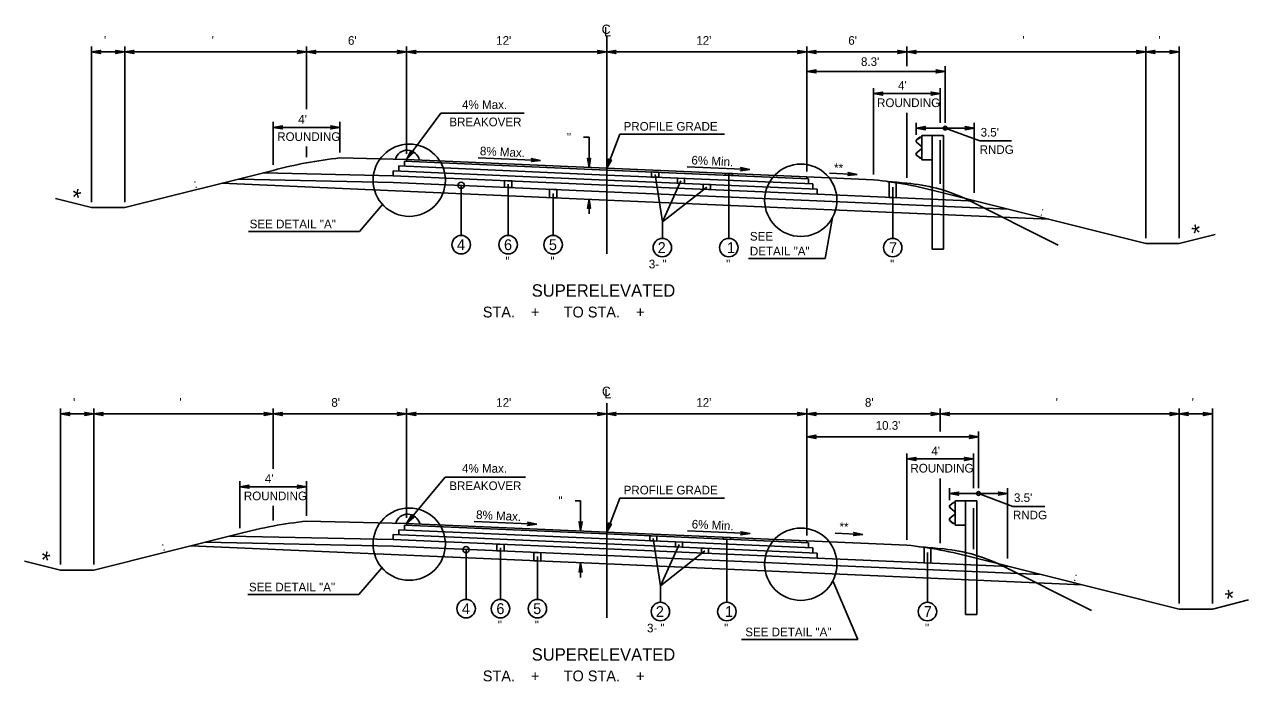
# Model space of a CAD drawing. Extents: x -540 to 1231, y -564 to 421.
# Drawn here: x 1028.3 to 1226.1, y -243.2 to -137 of the extents above; entities that cross this region are included whole.
import ezdxf

# ---------------------------------------------------------------- set-up
doc = ezdxf.new("R2010")
doc.units = 0
doc.layers.add('1', color=7, linetype='Continuous')
doc.layers.add('Des_ Drain_ Ftrs', color=7, linetype='Continuous')

msp = doc.modelspace()

# ---------------------------------------------------------------- linework, layer by layer
at = {"layer": '1'}
for p, q in [((1122.38, -174.05), (1122.38, -138.76)), ((1039.12, -165.67), (1039.12, -140.52)), ((1044.51, -141.4), (1039.12, -141.4)), ((1044.51, -165.67), (1044.51, -140.52)), ((1073.88, -141.4), (1044.51, -141.4)), ((1073.88, -150.65), (1073.88, -140.52)), ((1090.05, -141.4), (1073.88, -141.4)), ((1090.05, -157.9), (1090.05, -140.52)), ((1122.38, -141.4), (1090.05, -141.4)), ((1122.38, -141.4), (1154.71, -141.4)), ((1154.71, -160.72), (1154.71, -140.52)), ((1154.71, -141.4), (1170.87, -141.4)), ((1170.87, -143.69), (1170.87, -140.52)), ((1170.87, -141.4), (1209.46, -141.4)), ((1209.46, -171.5), (1209.46, -140.52)), ((1209.46, -141.4), (1214.85, -141.4)), ((1214.85, -171.5), (1214.85, -140.52)), ((1177.07, -152.84), (1177.07, -143.69)), ((1154.71, -144.57), (1177.07, -144.57)), ((1177.07, -144.57), (1177.07, -151.71)), ((1165.48, -161.2), (1165.48, -147.26)), ((1165.48, -148.14), (1176.26, -148.14)), ((1176.26, -152.84), (1176.26, -147.26)), ((1090.04, -158.78), (1095.58, -151.32)), ((1109.06, -151.32), (1095.58, -151.32)), ((1170.87, -161.75), (1170.87, -151.26)), ((1068.49, -159.68), (1068.49, -152.73)), ((1079.27, -153.61), (1068.49, -153.61)), ((1079.27, -157.66), (1079.27, -152.73)), ((1172.38, -154.79), (1172.38, -152.84)), ((1172.38, -153.72), (1181.76, -153.72)), ((1177.07, -153.72), (1182.63, -155.79)), ((1181.76, -164.19), (1181.76, -152.84)), ((1119.52, -155.19), (1118.64, -155.19)), ((1119.52, -155.19), (1119.52, -160.07)), ((1122.38, -160.19), (1124.48, -154.72)), ((1141.4, -154.72), (1124.48, -154.72)), ((1172.44, -156.01), (1173.17, -156.65)), ((1172.97, -155.19), (1172.46, -155.58)), ((1172.46, -155.99), (1173.19, -156.62)), ((1172.99, -155.22), (1172.48, -155.6)), ((1173.29, -155.13), (1172.97, -155.19)), ((1173.29, -155.16), (1172.99, -155.22)), ((1173.29, -154.91), (1173.29, -158.84)), ((1173.29, -154.91), (1174.97, -154.91)), ((1174.97, -154.91), (1174.97, -173.3)), ((1176.8, -154.91), (1174.97, -154.91)), ((1176.26, -162.72), (1176.26, -155.64)), ((1176.8, -154.91), (1176.8, -173.3)), ((1182.63, -155.79), (1187.78, -155.79)), ((1073.88, -158.44), (1073.88, -156.67)), ((1173.17, -157.1), (1172.44, -157.73)), ((1173.19, -157.12), (1172.46, -157.75)), ((1172.46, -158.16), (1172.97, -158.55)), ((1172.48, -158.14), (1172.99, -158.53)), ((1173.26, -156.83), (1173.26, -156.91)), ((1173.29, -156.83), (1173.29, -156.91)), ((1079.27, -158.54), (1090.04, -158.78)), ((1122.38, -161.3), (1088.78, -159.83)), ((1088.78, -160.64), (1088.78, -159.83)), ((1122.38, -160.49), (1089.7, -159.07)), ((1089.7, -159.87), (1089.7, -159.07)), ((1122.38, -160.19), (1090.04, -158.78)), ((1090.04, -158.78), (1090.04, -159.08)), ((1101.58, -158.51), (1111.69, -158.95)), ((1135.36, -159.98), (1145.47, -160.42)), ((1172.97, -158.55), (1173.29, -158.61)), ((1172.99, -158.53), (1173.29, -158.58)), ((1173.29, -158.84), (1174.97, -158.84)), ((1068.49, -160.56), (1044.51, -166.55)), ((1062.93, -161.95), (1087.86, -162.49)), ((1066.9, -160.95), (1087.87, -161.41)), ((1122.38, -162.11), (1087.86, -160.6)), ((1087.86, -161.41), (1087.86, -160.6)), ((1122.38, -162.92), (1087.87, -161.41)), ((1154.71, -161.61), (1122.38, -160.19)), ((1154.95, -161.91), (1122.38, -160.49)), ((1155.65, -162.75), (1122.38, -161.3)), ((1156.35, -163.59), (1122.38, -162.11)), ((1130.2, -161.24), (1131.36, -168.87)), ((1142.1, -161.21), (1142.1, -171.55)), ((1165.48, -162.08), (1154.71, -161.61)), ((1154.71, -161.61), (1154.71, -161.91)), ((1154.95, -161.91), (1154.95, -162.72)), ((1162.85, -161.21), (1158.35, -161.02)), ((1122.38, -165.35), (1060.19, -162.63)), ((1122.38, -164), (1087.86, -162.49)), ((1098.86, -162.97), (1098.86, -171.08)), ((1106.45, -162.76), (1106.45, -171.08)), ((1156.36, -164.4), (1122.38, -162.92)), ((1156.31, -165.48), (1122.38, -164)), ((1134.37, -162.22), (1131.36, -168.87)), ((1138.55, -163.24), (1131.36, -168.87)), ((1155.65, -162.75), (1155.65, -163.56)), ((1156.35, -163.59), (1156.35, -164.4)), ((1168.58, -163.26), (1168.58, -171.55)), ((1172.38, -162.85), (1172.38, -162.85)), ((1176.26, -164.08), (1209.46, -172.38)), ((1033.3, -165.09), (1039.12, -166.55)), ((1082.43, -170.41), (1086.17, -166.09)), ((1113.72, -164.29), (1113.72, -171.08)), ((1119.52, -165.22), (1119.52, -167.59)), ((1193.78, -168.46), (1122.38, -165.35)), ((1187.24, -166.83), (1156.31, -165.48)), ((1182.01, -165.52), (1156.35, -164.4)), ((1180.26, -165.09), (1195.31, -172.61)), ((1044.51, -166.55), (1039.12, -166.55)), ((1131.36, -168.87), (1131.36, -171.55)), ((1158.86, -168.17), (1157.68, -174.81)), ((1064.5, -170.41), (1082.43, -170.41)), ((1220.67, -170.93), (1214.85, -172.38)), ((1176.8, -173.3), (1174.97, -173.3)), ((1209.46, -172.38), (1214.85, -172.38)), ((1145.27, -174.81), (1157.68, -174.81)), ((1034.14, -224.27), (1034.14, -199.03)), ((1039.52, -224.27), (1039.52, -199.03)), ((1068.49, -208.8), (1068.49, -199.03)), ((1090.05, -216.72), (1090.05, -199.03)), ((1122.38, -232.87), (1122.38, -198.15)), ((1154.71, -219.54), (1154.71, -199.03)), ((1176.26, -202.74), (1176.26, -199.03)), ((1214.85, -230.56), (1214.85, -199.03)), ((1220.23, -230.56), (1220.23, -199.03)), ((1039.52, -199.91), (1034.14, -199.91)), ((1068.49, -199.91), (1039.52, -199.91)), ((1090.05, -199.91), (1068.49, -199.91)), ((1122.38, -199.91), (1090.05, -199.91)), ((1122.38, -199.91), (1154.71, -199.91)), ((1154.71, -199.91), (1176.26, -199.91)), ((1176.26, -199.91), (1214.85, -199.91)), ((1214.85, -199.91), (1220.23, -199.91)), ((1154.71, -203.62), (1182.46, -203.62)), ((1182.46, -211.89), (1182.46, -202.74)), ((1170.87, -220.25), (1170.87, -206.31)), ((1170.87, -207.19), (1181.65, -207.19)), ((1181.65, -211.89), (1181.65, -206.31)), ((1063.11, -218.37), (1063.11, -210.8)), ((1073.88, -216.36), (1073.88, -210.8)), ((1090.04, -217.6), (1096.3, -210.12)), ((1109.27, -210.12), (1096.3, -210.12)), ((1176.26, -220.8), (1176.26, -210.34)), ((1073.88, -211.68), (1063.11, -211.68)), ((1122.38, -219.01), (1124.5, -213.5)), ((1141.42, -213.5), (1124.5, -213.5)), ((1177.76, -213.84), (1177.76, -211.89)), ((1177.76, -212.77), (1187.15, -212.77)), ((1182.46, -212.77), (1188.01, -214.85)), ((1187.15, -223.26), (1187.15, -211.89)), ((1068.49, -217.14), (1068.49, -214.76)), ((1118.15, -213.95), (1117.27, -213.95)), ((1118.15, -213.95), (1118.15, -218.82)), ((1177.83, -215.06), (1178.56, -215.7)), ((1178.36, -214.24), (1177.85, -214.63)), ((1177.85, -215.04), (1178.58, -215.68)), ((1178.37, -214.27), (1177.86, -214.65)), ((1178.68, -214.19), (1178.36, -214.24)), ((1178.68, -214.22), (1178.37, -214.27)), ((1178.68, -213.96), (1178.68, -217.89)), ((1178.68, -213.96), (1180.36, -213.96)), ((1180.36, -213.96), (1180.36, -232.35)), ((1182.19, -213.96), (1180.36, -213.96)), ((1181.65, -221.77), (1181.65, -215.12)), ((1182.19, -213.96), (1182.19, -232.35)), ((1188.01, -214.85), (1193.17, -214.85)), ((1073.88, -217.24), (1090.04, -217.6)), ((1100.95, -217.3), (1111.07, -217.74)), ((1178.56, -216.15), (1177.83, -216.78)), ((1178.58, -216.17), (1177.85, -216.81)), ((1177.85, -217.22), (1178.36, -217.61)), ((1177.86, -217.19), (1178.37, -217.58)), ((1178.65, -215.89), (1178.65, -215.96)), ((1178.68, -215.89), (1178.68, -215.96)), ((1063.11, -219.25), (1039.52, -225.15)), ((1122.38, -220.93), (1087.86, -219.42)), ((1087.86, -220.23), (1087.86, -219.42)), ((1122.38, -220.12), (1088.78, -218.65)), ((1088.78, -219.46), (1088.78, -218.65)), ((1122.38, -219.31), (1089.7, -217.88)), ((1089.7, -218.69), (1089.7, -217.88)), ((1122.38, -219.01), (1090.04, -217.6)), ((1090.04, -217.6), (1090.04, -217.9)), ((1154.71, -220.42), (1122.38, -219.01)), ((1154.95, -220.73), (1122.38, -219.31)), ((1135.42, -218.81), (1145.53, -219.25)), ((1163.75, -219.38), (1159.26, -219.18)), ((1178.36, -217.61), (1178.68, -217.66)), ((1178.37, -217.58), (1178.68, -217.63)), ((1178.68, -217.89), (1180.36, -217.89)), ((1122.38, -224.16), (1055.21, -221.23)), ((1057.54, -220.65), (1087.86, -221.31)), ((1061.51, -219.65), (1087.86, -220.23)), ((1122.38, -221.74), (1087.86, -220.23)), ((1122.38, -222.81), (1087.86, -221.31)), ((1155.65, -221.57), (1122.38, -220.12)), ((1156.35, -222.41), (1122.38, -220.93)), ((1129.89, -220.04), (1131.05, -227.67)), ((1134.07, -221.02), (1131.05, -227.67)), ((1141.78, -220.03), (1141.78, -230.37)), ((1170.87, -221.13), (1154.71, -220.42)), ((1154.71, -220.42), (1154.71, -220.72)), ((1154.95, -220.73), (1154.95, -221.54)), ((1099.66, -221.84), (1099.66, -229.9)), ((1105.21, -221.55), (1105.21, -229.9)), ((1111.18, -222.98), (1111.18, -229.9)), ((1156.35, -223.22), (1122.38, -221.74)), ((1156.35, -224.3), (1122.38, -222.81)), ((1138.24, -222.04), (1131.05, -227.67)), ((1155.65, -221.57), (1155.65, -222.38)), ((1156.35, -222.41), (1156.35, -223.22)), ((1187.4, -224.58), (1156.35, -223.22)), ((1174.19, -222.28), (1174.19, -230.37)), ((1177.76, -221.9), (1177.76, -221.9)), ((1181.65, -223.14), (1214.85, -231.44)), ((1028.31, -223.69), (1034.14, -225.15)), ((1039.52, -225.15), (1034.14, -225.15)), ((1082.31, -229.1), (1086.05, -224.78)), ((1118.15, -223.98), (1118.15, -226.34)), ((1156.35, -225.65), (1122.38, -224.16)), ((1192.63, -225.88), (1156.35, -224.3)), ((1185.65, -224.14), (1200.7, -231.66)), ((1199.16, -227.52), (1156.35, -225.65)), ((1158.91, -226.89), (1162.96, -236.36)), ((1064.38, -229.1), (1082.31, -229.1)), ((1131.05, -227.67), (1131.05, -230.37)), ((1226.06, -229.98), (1220.23, -231.44)), ((1182.19, -232.35), (1180.36, -232.35)), ((1214.85, -231.44), (1220.23, -231.44)), ((1144.17, -236.36), (1162.96, -236.36))]:
    msp.add_line(p, q, dxfattribs=at)
for points in [[(1129.62, -160.81), (1130.77, -160.86), (1130.77, -161.67), (1129.62, -161.62)], [(1133.8, -161.8), (1134.94, -161.85), (1134.94, -162.66), (1133.8, -162.61)], [(1141.53, -161.03), (1142.68, -161.08), (1142.68, -161.38), (1141.53, -161.33)], [(1105.88, -162.2), (1107.02, -162.25), (1107.02, -163.33), (1105.88, -163.28)], [(1113.14, -163.59), (1114.29, -163.64), (1114.29, -164.99), (1113.14, -164.94)], [(1137.97, -162.79), (1139.12, -162.84), (1139.12, -163.65), (1137.97, -163.6)], [(1168.01, -162.38), (1169.15, -162.56), (1169.15, -164.96), (1168.01, -164.91)], [(1104.64, -220.96), (1105.78, -221.01), (1105.78, -222.09), (1104.64, -222.04)], [(1129.32, -219.61), (1130.46, -219.66), (1130.46, -220.47), (1129.32, -220.42)], [(1133.49, -220.6), (1134.64, -220.65), (1134.64, -221.46), (1133.49, -221.41)], [(1141.2, -219.83), (1142.35, -219.88), (1142.35, -220.18), (1141.2, -220.13)], [(1173.66, -221.47), (1174.72, -221.64), (1174.72, -224.02), (1173.66, -223.98)], [(1110.61, -222.3), (1111.75, -222.35), (1111.75, -223.7), (1110.61, -223.65)], [(1137.67, -221.59), (1138.82, -221.64), (1138.82, -222.45), (1137.67, -222.4)]]:
    msp.add_lwpolyline(points, close=True, dxfattribs=at)
for centre, radius in [((1177.07, -153.72), 0.3), ((1090.47, -162.14), 5.84), ((1153.73, -165.38), 5.84), ((1098.86, -162.97), 0.5), ((1098.86, -172.56), 1.49), ((1106.45, -172.56), 1.49), ((1113.72, -172.56), 1.49), ((1131.36, -173.03), 1.49), ((1142.1, -173.03), 1.49), ((1168.58, -173.03), 1.49), ((1182.46, -212.77), 0.3), ((1090.47, -220.96), 5.84), ((1153.73, -224.2), 5.84), ((1099.66, -221.84), 0.5), ((1099.66, -231.38), 1.49), ((1105.21, -231.38), 1.49), ((1111.18, -231.38), 1.49), ((1131.05, -231.85), 1.49), ((1141.78, -231.85), 1.49), ((1174.19, -231.85), 1.49)]:
    msp.add_circle(centre, radius, dxfattribs=at)
for centre, radius, start, end in [((1172.62, -155.8), 0.278, 126.9799, 229.021), ((1172.62, -155.8), 0.249, 126.9799, 229.021), ((1090.15, -159.28), 1.99, 11.9626, 164.1977), ((1172.62, -157.94), 0.278, 130.979, 233.0201), ((1172.62, -157.94), 0.249, 130.979, 233.0201), ((1173.01, -156.83), 0.249, 0, 49.0365), ((1173.01, -156.91), 0.249, 310.9635, 0), ((1173.01, -156.83), 0.278, 0, 49.0365), ((1173.01, -156.91), 0.278, 310.9635, 0), ((1086.17, -225.38), 67.19, 95.8911, 105.2497), ((1158.6, -228.91), 67.19, 74.7602, 84.1188), ((1160.05, -263.3), 101.24, 83.8633, 85.6775), ((1168.75, -189.92), 27.37, 65.1374, 85.5513), ((1178.01, -214.85), 0.278, 126.9799, 229.021), ((1178.01, -214.85), 0.249, 126.9799, 229.021), ((1080.78, -284.08), 67.19, 95.8897, 105.2483), ((1090.2, -218.11), 2, 12.248, 163.77), ((1178.01, -216.99), 0.278, 130.979, 233.0201), ((1178.01, -216.99), 0.249, 130.979, 233.0201), ((1178.4, -215.89), 0.249, 0, 49.0365), ((1178.4, -215.96), 0.249, 310.9635, 0), ((1178.4, -215.89), 0.278, 0, 49.0365), ((1178.4, -215.96), 0.278, 310.9635, 0), ((1163.99, -287.96), 67.19, 74.7602, 84.1188), ((1165.44, -322.35), 101.24, 83.8633, 85.6775), ((1174.14, -248.97), 27.37, 65.1374, 85.5513)]:
    msp.add_arc(centre, radius, start, end, dxfattribs=at)
at = {"layer": 'Des_ Drain_ Ftrs'}
for points in [[(1039.12, -141.4), (1040.61, -141.65), (1040.32, -141.4), (1040.61, -141.16)], [(1044.51, -141.4), (1043.02, -141.65), (1043.32, -141.4), (1043.02, -141.16)], [(1044.51, -141.4), (1046, -141.65), (1045.71, -141.4), (1046, -141.16)], [(1073.88, -141.4), (1072.39, -141.65), (1072.69, -141.4), (1072.39, -141.16)], [(1073.88, -141.4), (1075.37, -141.65), (1075.08, -141.4), (1075.37, -141.16)], [(1090.05, -141.4), (1088.56, -141.65), (1088.85, -141.4), (1088.56, -141.16)], [(1090.05, -141.4), (1091.54, -141.65), (1091.24, -141.4), (1091.54, -141.16)], [(1122.38, -141.4), (1120.89, -141.65), (1121.18, -141.4), (1120.89, -141.16)], [(1122.38, -141.4), (1123.86, -141.65), (1123.57, -141.4), (1123.86, -141.16)], [(1154.71, -141.4), (1153.22, -141.65), (1153.51, -141.4), (1153.22, -141.16)], [(1154.71, -141.4), (1156.19, -141.65), (1155.9, -141.4), (1156.19, -141.16)], [(1170.87, -141.4), (1169.38, -141.65), (1169.68, -141.4), (1169.38, -141.16)], [(1170.87, -141.4), (1172.36, -141.65), (1172.06, -141.4), (1172.36, -141.16)], [(1209.46, -141.4), (1207.97, -141.65), (1208.26, -141.4), (1207.97, -141.16)], [(1209.46, -141.4), (1210.95, -141.65), (1210.65, -141.4), (1210.95, -141.16)], [(1214.85, -141.4), (1213.36, -141.65), (1213.65, -141.4), (1213.36, -141.16)], [(1154.71, -144.57), (1156.2, -144.81), (1155.9, -144.57), (1156.2, -144.32)], [(1177.07, -144.57), (1175.58, -144.81), (1175.87, -144.57), (1175.58, -144.32)], [(1165.48, -148.14), (1166.97, -148.39), (1166.68, -148.14), (1166.97, -147.89)], [(1176.26, -148.14), (1174.77, -148.39), (1175.07, -148.14), (1174.77, -147.89)], [(1068.49, -153.61), (1069.98, -153.86), (1069.69, -153.61), (1069.98, -153.36)], [(1079.27, -153.61), (1077.78, -153.86), (1078.08, -153.61), (1077.78, -153.36)], [(1172.38, -153.72), (1173.86, -153.97), (1173.57, -153.72), (1173.86, -153.47)], [(1181.76, -153.72), (1180.27, -153.97), (1180.57, -153.72), (1180.27, -153.47)], [(1090.04, -158.78), (1091.13, -157.73), (1090.75, -157.82), (1090.73, -157.44)], [(1111.69, -158.95), (1110.2, -159.14), (1110.5, -158.9), (1110.22, -158.64)], [(1119.52, -160.07), (1119.77, -158.58), (1119.52, -158.87), (1119.27, -158.58)], [(1122.38, -160.19), (1123.14, -158.89), (1122.8, -159.08), (1122.68, -158.71)], [(1145.47, -160.42), (1143.97, -160.6), (1144.28, -160.37), (1144, -160.11)], [(1162.85, -161.21), (1161.35, -161.4), (1161.66, -161.16), (1161.37, -160.9)], [(1119.52, -165.22), (1119.77, -166.71), (1119.52, -166.41), (1119.27, -166.71)], [(1034.14, -199.91), (1035.62, -200.16), (1035.33, -199.91), (1035.62, -199.67)], [(1039.52, -199.91), (1038.04, -200.16), (1038.33, -199.91), (1038.04, -199.67)], [(1039.52, -199.91), (1041.01, -200.16), (1040.72, -199.91), (1041.01, -199.67)], [(1068.49, -199.91), (1067.01, -200.16), (1067.3, -199.91), (1067.01, -199.67)], [(1068.49, -199.91), (1069.98, -200.16), (1069.69, -199.91), (1069.98, -199.67)], [(1090.05, -199.91), (1088.56, -200.16), (1088.85, -199.91), (1088.56, -199.67)], [(1090.05, -199.91), (1091.54, -200.16), (1091.24, -199.91), (1091.54, -199.67)], [(1122.38, -199.91), (1120.89, -200.16), (1121.18, -199.91), (1120.89, -199.67)], [(1122.38, -199.91), (1123.86, -200.16), (1123.57, -199.91), (1123.86, -199.67)], [(1154.71, -199.91), (1153.22, -200.16), (1153.51, -199.91), (1153.22, -199.67)], [(1154.71, -199.91), (1156.19, -200.16), (1155.9, -199.91), (1156.19, -199.67)], [(1176.26, -199.91), (1174.77, -200.16), (1175.07, -199.91), (1174.77, -199.67)], [(1176.26, -199.91), (1177.75, -200.16), (1177.45, -199.91), (1177.75, -199.67)], [(1214.85, -199.91), (1213.36, -200.16), (1213.65, -199.91), (1213.36, -199.67)], [(1214.85, -199.91), (1216.33, -200.16), (1216.04, -199.91), (1216.33, -199.67)], [(1220.23, -199.91), (1218.75, -200.16), (1219.04, -199.91), (1218.75, -199.67)], [(1154.71, -203.62), (1156.19, -203.87), (1155.9, -203.62), (1156.19, -203.37)], [(1182.46, -203.62), (1180.97, -203.87), (1181.26, -203.62), (1180.97, -203.37)], [(1170.87, -207.19), (1172.36, -207.44), (1172.06, -207.19), (1172.36, -206.94)], [(1181.65, -207.19), (1180.16, -207.44), (1180.45, -207.19), (1180.16, -206.94)], [(1063.11, -211.68), (1064.59, -211.93), (1064.3, -211.68), (1064.59, -211.43)], [(1073.88, -211.68), (1072.39, -211.93), (1072.69, -211.68), (1072.39, -211.43)], [(1177.76, -212.77), (1179.25, -213.02), (1178.96, -212.77), (1179.25, -212.53)], [(1187.15, -212.77), (1185.66, -213.02), (1185.96, -212.77), (1185.66, -212.53)], [(1090.04, -217.6), (1091.19, -216.62), (1090.81, -216.68), (1090.81, -216.3)], [(1111.07, -217.74), (1109.57, -217.92), (1109.87, -217.69), (1109.59, -217.42)], [(1118.15, -218.82), (1118.4, -217.34), (1118.15, -217.63), (1117.9, -217.34)], [(1122.38, -219.01), (1123.14, -217.71), (1122.8, -217.89), (1122.68, -217.53)], [(1145.53, -219.25), (1144.03, -219.44), (1144.34, -219.2), (1144.05, -218.94)], [(1163.75, -219.38), (1162.26, -219.56), (1162.56, -219.32), (1162.28, -219.06)], [(1118.15, -223.98), (1118.4, -225.46), (1118.15, -225.17), (1117.9, -225.46)]]:
    msp.add_lwpolyline(points, close=True, dxfattribs=at)

# ---------------------------------------------------------------- texts
at = {"layer": '1'}
for s, height, p in [(" '", 1.4, (1040.62, -140.25)), ("  '", 1.4, (1057.5, -140.25)), ("6'", 1.4, (1080.57, -140.25)), ("12'", 1.4, (1104.52, -140.25)), ("12'", 1.4, (1136.85, -140.25)), ("6'", 1.4, (1161.4, -140.25)), ("  '", 1.4, (1188.47, -140.25)), (" '", 1.4, (1210.96, -140.25)), ("8.3'", 1.4, (1163.45, -143.68)), ("4'", 1.4, (1169.44, -147.52)), ('4% Max.', 1.4, (1099, -150.62)), ('ROUNDING', 1.4, (1166.05, -150.32)), ("4'", 1.4, (1072.53, -152.99)), ('BREAKOVER', 1.4, (1096.95, -153.42)), ('PROFILE GRADE', 1.4, (1125.1, -154.14)), ("3.5'", 1.4, (1182.78, -155.09)), ('ROUNDING', 1.4, (1069.14, -155.79)), ('RNDG', 1.4, (1182.62, -157.89)), ('SEE DETAIL "A"', 1.4, (1064.69, -169.91)), ('4', 1.75, (1098.18, -173.44)), ('6', 1.75, (1105.78, -173.44)), ('5', 1.75, (1113.03, -173.44)), ('SEE', 1.4, (1145.5, -171.9)), ('2', 1.75, (1130.61, -173.91)), ('1', 1.75, (1141.8, -173.91)), ('DETAIL "A"', 1.4, (1145.5, -174.3)), ('7', 1.75, (1167.99, -173.91)), (' "', 1.4, (1105.51, -175.92)), (' "', 1.4, (1112.77, -175.92)), ('3- "', 1.4, (1129.18, -176.39)), (' "', 1.4, (1141.16, -176.39)), (' "', 1.4, (1167.64, -176.39)), ('SUPERELEVATED', 2, (1110.26, -180.96)), ('STA.    +      TO STA.    +     ', 1.75, (1102.35, -184.32)), (" '", 1.4, (1035.63, -198.76)), ("  '", 1.4, (1052.31, -198.76)), ("8'", 1.4, (1077.88, -198.76)), ("12'", 1.4, (1104.52, -198.76)), ("12'", 1.4, (1136.85, -198.76)), ("8'", 1.4, (1164.09, -198.76)), ("  '", 1.4, (1193.86, -198.76)), (" '", 1.4, (1216.35, -198.76)), ("10.3'", 1.4, (1165.82, -202.47)), ("4'", 1.4, (1174.83, -206.58)), ('4% Max.', 1.4, (1098.99, -209.42)), ('ROUNDING', 1.4, (1171.44, -209.38)), ("4'", 1.4, (1067.14, -211.06)), ('BREAKOVER', 1.4, (1096.94, -212.22)), ('PROFILE GRADE', 1.4, (1125.11, -212.92)), ('ROUNDING', 1.4, (1063.75, -213.86)), ("3.5'", 1.4, (1188.17, -214.15)), ('RNDG', 1.4, (1188, -216.95)), ('SEE DETAIL "A"', 1.4, (1064.57, -228.59)), ('4', 1.75, (1098.98, -232.26)), ('6', 1.75, (1104.55, -232.26)), ('5', 1.75, (1110.49, -232.26)), ('2', 1.75, (1130.31, -232.73)), ('1', 1.75, (1141.47, -232.73)), ('7', 1.75, (1173.6, -232.73)), (' "', 1.4, (1104.27, -234.74)), (' "', 1.4, (1110.24, -234.74)), ('3- "', 1.4, (1128.88, -235.21)), (' "', 1.4, (1140.83, -235.21)), ('SEE DETAIL "A"', 1.4, (1144.76, -235.85)), ('  "', 1.4, (1172.75, -235.21)), ('SUPERELEVATED', 2, (1110.26, -239.78)), ('STA.    +      TO STA.    +     ', 1.75, (1102.35, -243.13))]:
    msp.add_text(s, height=height, dxfattribs=at).set_placement(p)
for s, height, rotation, p in [('  "', 1.4, 0.1438, (1114.91, -155.89)), ('8% Max.', 1.4, 357.3764, (1101.86, -158.09)), ('6% Min.', 1.4, 357.3728, (1136.03, -159.58)), ('**', 1.4, 357.2167, (1159.06, -160.81)), ('*', 2.8, 347.1521, (1035.61, -166.12)), (' : ', 1.4, 14.2282, (1055.32, -163.57)), (' : ', 1.4, 345.7718, (1191.81, -167.68)), ('*', 2.8, 12.8479, (1217.31, -172.19)), ('  "', 1.4, 0.1438, (1113.54, -214.65)), ('8% Max.', 1.4, 357.3762, (1101.24, -216.88)), ('6% Min.', 1.4, 357.3731, (1136.08, -218.41)), ('**', 1.4, 357.2167, (1159.94, -218.81)), (' : ', 1.4, 14.2282, (1050.14, -222.22)), ('*', 2.8, 347.1521, (1030.62, -224.72)), (' : ', 1.4, 345.7718, (1197.2, -226.73)), ('*', 2.8, 12.8479, (1222.7, -231.24))]:
    msp.add_text(s, height=height, rotation=rotation, dxfattribs=at).set_placement(p)
at = {"layer": 'Des_ Drain_ Ftrs'}
for s, p in [('C', (1121.55, -138.49)), ('L', (1121.95, -138.89)), ('C', (1121.6, -197.01)), ('L', (1121.99, -197.4))]:
    msp.add_text(s, height=1.5, dxfattribs=at).set_placement(p)

doc.saveas('drawing.dxf')
